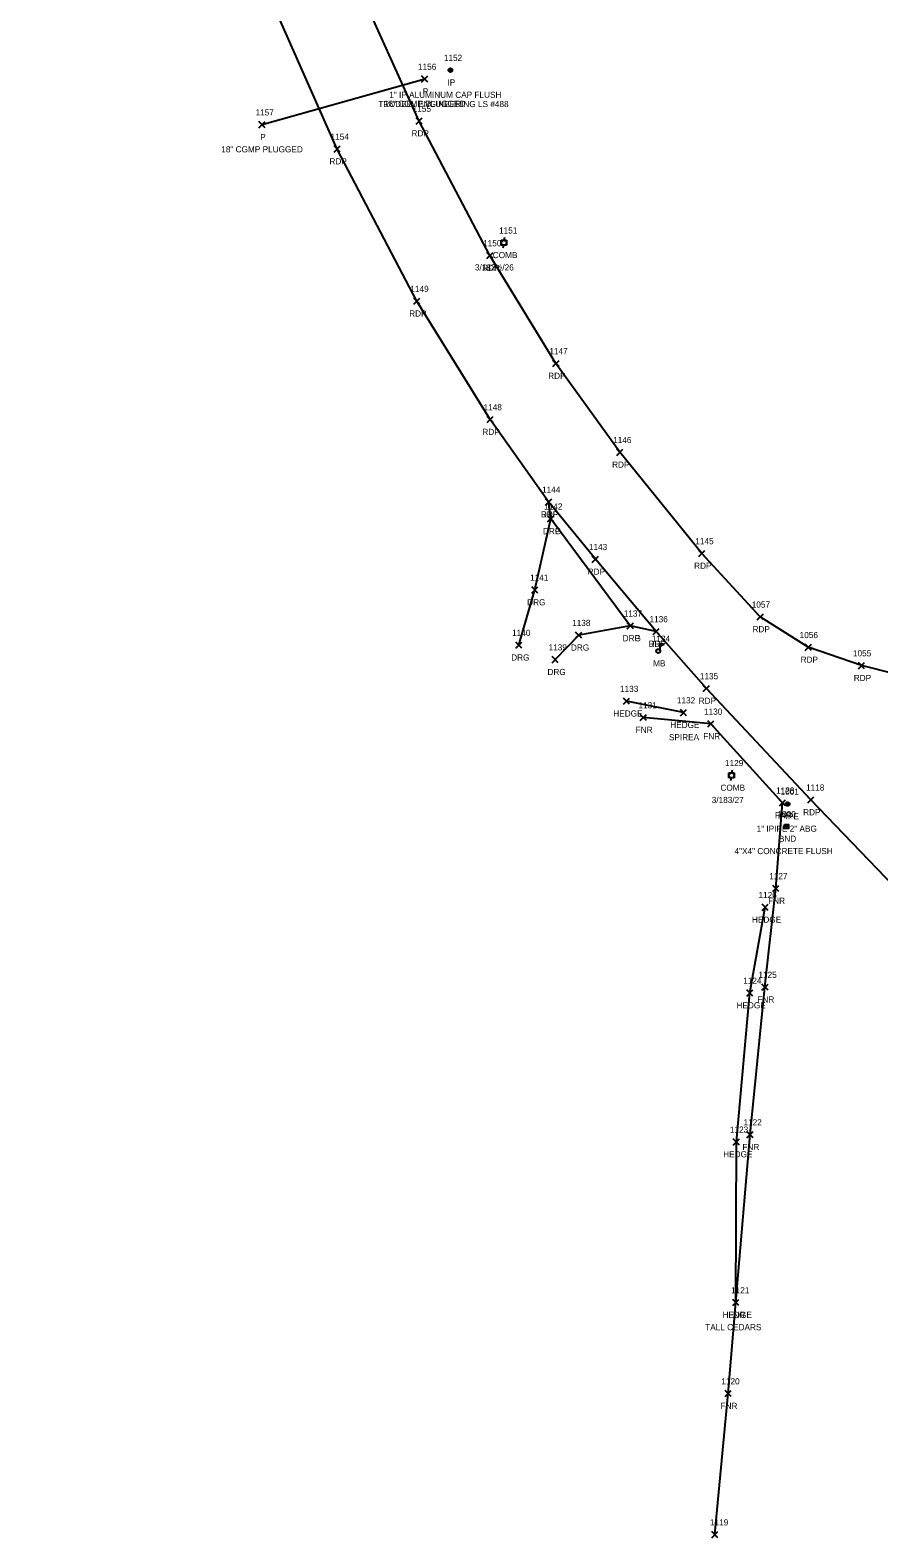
# Model space of a CAD drawing. Extents: x 1503463 to 1505240, y 712171 to 717196.
# Drawn here: x 1504621.3 to 1504897.3, y 713821.7 to 714311.7 of the extents above; entities that cross this region are included whole.
import ezdxf

# ---------------------------------------------------------------- set-up
doc = ezdxf.new("R2010")
doc.units = 0
for name, color, linetype in [('D_A', 7, 'Continuous'), ('D_C', 7, 'Continuous'), ('D_I', 7, 'Continuous'), ('D_TIC', 7, 'Continuous'), ('DCP', 7, 'Continuous'), ('L_A', 7, 'Continuous'), ('L_C', 7, 'Continuous'), ('L_I', 7, 'Continuous'), ('L_TIC', 7, 'Continuous'), ('LAHR', 7, 'Continuous'), ('LFNC', 7, 'Continuous'), ('LMB', 7, 'Continuous'), ('M_A', 7, 'Continuous'), ('M_C', 7, 'Continuous'), ('M_I', 7, 'Continuous'), ('MHBP', 7, 'Continuous'), ('MPIP', 7, 'Continuous'), ('MPIR', 7, 'Continuous'), ('P_A', 7, 'Continuous'), ('P_I', 7, 'Continuous'), ('P_TIC', 7, 'Continuous'), ('PET', 7, 'Continuous'), ('R_A', 7, 'Continuous'), ('R_I', 7, 'Continuous'), ('R_TIC', 7, 'Continuous'), ('RDG', 7, 'Continuous'), ('RDP', 7, 'Continuous'), ('U_A', 7, 'Continuous'), ('U_C', 7, 'Continuous'), ('U_I', 7, 'Continuous'), ('UP', 7, 'Continuous')]:
    doc.layers.add(name, color=color, linetype=linetype)

msp = doc.modelspace()

# ---------------------------------------------------------------- linework, layer by layer
at = {"layer": 'D_TIC'}
for points in [[(1504748.64, 714294.8), (1504750.64, 714296.8)], [(1504750.64, 714294.8), (1504748.64, 714296.8)], [(1504695.75, 714279.97), (1504697.75, 714281.97)], [(1504697.75, 714279.97), (1504695.75, 714281.97)]]:
    msp.add_lwpolyline(points, dxfattribs=at)
at = {"layer": 'DCP'}
msp.add_lwpolyline([(1504749.64, 714295.8), (1504696.75, 714280.97)], dxfattribs=at)
at = {"layer": 'L_TIC'}
for points in [[(1504814.26, 714092.64), (1504816.26, 714094.64)], [(1504816.26, 714092.64), (1504814.26, 714094.64)], [(1504819.72, 714087.31), (1504821.72, 714089.31)], [(1504821.72, 714087.31), (1504819.72, 714089.31)], [(1504832.78, 714088.92), (1504834.78, 714090.92)], [(1504834.78, 714088.92), (1504832.78, 714090.92)], [(1504841.67, 714085.25), (1504843.67, 714087.25)], [(1504843.67, 714085.25), (1504841.67, 714087.25)], [(1504865.01, 714059.61), (1504867.01, 714061.61)], [(1504867.01, 714059.61), (1504865.01, 714061.61)], [(1504862.79, 714031.77), (1504864.79, 714033.77)], [(1504864.79, 714031.77), (1504862.79, 714033.77)], [(1504859.36, 714025.65), (1504861.36, 714027.65)], [(1504861.36, 714025.65), (1504859.36, 714027.65)], [(1504859.27, 713999.7), (1504861.27, 714001.7)], [(1504861.27, 713999.7), (1504859.27, 714001.7)], [(1504854.33, 713997.81), (1504856.33, 713999.81)], [(1504856.33, 713997.81), (1504854.33, 713999.81)], [(1504854.42, 713951.78), (1504856.42, 713953.78)], [(1504856.42, 713951.78), (1504854.42, 713953.78)], [(1504849.99, 713949.4), (1504851.99, 713951.4)], [(1504851.99, 713949.4), (1504849.99, 713951.4)], [(1504849.82, 713897.2), (1504851.82, 713899.2)], [(1504851.82, 713897.2), (1504849.82, 713899.2)], [(1504849.82, 713897.2), (1504851.82, 713899.2)], [(1504851.82, 713897.2), (1504849.82, 713899.2)], [(1504847.3, 713867.63), (1504849.3, 713869.63)], [(1504849.3, 713867.63), (1504847.3, 713869.63)], [(1504842.97, 713821.78), (1504844.97, 713823.78)], [(1504844.97, 713821.78), (1504842.97, 713823.78)]]:
    msp.add_lwpolyline(points, dxfattribs=at)
at = {"layer": 'LAHR'}
for points in [[(1504833.78, 714089.92), (1504815.26, 714093.64)], [(1504850.82, 713898.2), (1504850.99, 713950.4), (1504855.33, 713998.81), (1504860.36, 714026.65)]]:
    msp.add_lwpolyline(points, dxfattribs=at)
at = {"layer": 'LFNC'}
msp.add_lwpolyline([(1504843.97, 713822.78), (1504848.3, 713868.63), (1504850.82, 713898.2), (1504855.42, 713952.78), (1504860.27, 714000.7), (1504863.79, 714032.77), (1504866.01, 714060.61), (1504842.67, 714086.25), (1504820.72, 714088.31)], dxfattribs=at)
at = {"layer": 'LMB'}
for p, q in [((1504825.59, 714109.93), (1504825.59, 714109.93)), ((1504826.24, 714112.53), (1504827.54, 714112.15)), ((1504826.25, 714109.94), (1504826.25, 714112.53)), ((1504826.25, 714111.63), (1504827.53, 714112.14))]:
    msp.add_line(p, q, dxfattribs=at)
msp.add_circle((1504825.59, 714109.93), 0.656, dxfattribs=at)
at = {"layer": 'MHBP'}
msp.add_lwpolyline([(1504866.68, 714053.56), (1504867.93, 714053.56), (1504867.93, 714052.31), (1504866.68, 714052.31)], close=True, dxfattribs=at)
msp.add_circle((1504867.31, 714052.93), 0.0833, dxfattribs=at)
at = {"layer": 'MPIP'}
for radius in [0.625, 0.0833]:
    msp.add_circle((1504867.63, 714060.21), radius, dxfattribs=at)
at = {"layer": 'MPIR'}
for radius in [0.625, 0.0833]:
    msp.add_circle((1504757.99, 714298.69), radius, dxfattribs=at)
at = {"layer": 'P_TIC'}
for points in [[(1504746.85, 714281.15), (1504748.85, 714283.15)], [(1504748.85, 714281.15), (1504746.85, 714283.15)], [(1504720.17, 714272.06), (1504722.17, 714274.06)], [(1504722.17, 714272.06), (1504720.17, 714274.06)], [(1504769.85, 714237.46), (1504771.85, 714239.46)], [(1504771.85, 714237.46), (1504769.85, 714239.46)], [(1504746.1, 714222.61), (1504748.1, 714224.61)], [(1504748.1, 714222.61), (1504746.1, 714224.61)], [(1504791.31, 714202.38), (1504793.31, 714204.38)], [(1504793.31, 714202.38), (1504791.31, 714204.38)], [(1504769.9, 714184.14), (1504771.9, 714186.14)], [(1504771.9, 714184.14), (1504769.9, 714186.14)], [(1504812.09, 714173.5), (1504814.09, 714175.5)], [(1504814.09, 714173.5), (1504812.09, 714175.5)], [(1504788.93, 714157.37), (1504790.93, 714159.37)], [(1504790.93, 714157.37), (1504788.93, 714159.37)], [(1504804.14, 714138.73), (1504806.14, 714140.73)], [(1504806.14, 714138.73), (1504804.14, 714140.73)], [(1504838.76, 714140.64), (1504840.76, 714142.64)], [(1504840.76, 714140.64), (1504838.76, 714142.64)], [(1504857.75, 714120.03), (1504859.75, 714122.03)], [(1504859.75, 714120.03), (1504857.75, 714122.03)], [(1504823.92, 714115.29), (1504825.92, 714117.29)], [(1504825.92, 714115.29), (1504823.92, 714117.29)], [(1504873.38, 714110.13), (1504875.38, 714112.13)], [(1504875.38, 714110.13), (1504873.38, 714112.13)], [(1504890.67, 714104.18), (1504892.67, 714106.18)], [(1504892.67, 714104.18), (1504890.67, 714106.18)], [(1504840.23, 714096.76), (1504842.23, 714098.76)], [(1504842.23, 714096.76), (1504840.23, 714098.76)], [(1504874.2, 714060.56), (1504876.2, 714062.56)], [(1504876.2, 714060.56), (1504874.2, 714062.56)]]:
    msp.add_lwpolyline(points, dxfattribs=at)
at = {"layer": 'PET'}
for points in [[(1505179.12, 714062.13), (1505162.73, 714064.23), (1505117.1, 714071.16), (1505063.73, 714078.62), (1505006.07, 714088.04), (1504974.7, 714091.87), (1504950.76, 714094.03), (1504913.58, 714099.65), (1504891.67, 714105.18), (1504874.38, 714111.13), (1504858.75, 714121.03), (1504839.76, 714141.64), (1504813.09, 714174.5), (1504792.31, 714203.38), (1504770.85, 714238.46), (1504747.85, 714282.15), (1504727.38, 714327.5), (1504712.05, 714367.82), (1504697.71, 714414.83), (1504685.11, 714458.97), (1504676.94, 714491.61), (1504665.42, 714541.32), (1504657.14, 714577.6), (1504649.31, 714613.48)], [(1505055.48, 713804.69), (1505035.67, 713846.75), (1505012.25, 713888.12), (1504984.81, 713930.29), (1504955.82, 713968.98), (1504925.45, 714007.09), (1504902.19, 714033.47), (1504875.2, 714061.56), (1504841.23, 714097.76), (1504824.92, 714116.29), (1504805.14, 714139.73), (1504789.93, 714158.37), (1504770.9, 714185.14), (1504747.1, 714223.61), (1504721.17, 714273.06), (1504701.58, 714317.3), (1504686.12, 714357.97), (1504670.15, 714407.6), (1504658, 714450.85), (1504649.24, 714485.62), (1504637.84, 714534.39), (1504628.86, 714571.69), (1504621.33, 714603.22)]]:
    msp.add_lwpolyline(points, dxfattribs=at)
at = {"layer": 'R_TIC'}
for points in [[(1504788.93, 714157.37), (1504790.93, 714159.37)], [(1504790.93, 714157.37), (1504788.93, 714159.37)], [(1504789.6, 714151.9), (1504791.6, 714153.9)], [(1504791.6, 714151.9), (1504789.6, 714153.9)], [(1504789.6, 714151.9), (1504791.6, 714153.9)], [(1504791.6, 714151.9), (1504789.6, 714153.9)], [(1504784.46, 714128.77), (1504786.46, 714130.77)], [(1504786.46, 714128.77), (1504784.46, 714130.77)], [(1504815.5, 714117.1), (1504817.5, 714119.1)], [(1504817.5, 714117.1), (1504815.5, 714119.1)], [(1504815.5, 714117.1), (1504817.5, 714119.1)], [(1504817.5, 714117.1), (1504815.5, 714119.1)], [(1504798.7, 714114.06), (1504800.7, 714116.06)], [(1504800.7, 714114.06), (1504798.7, 714116.06)], [(1504823.92, 714115.29), (1504825.92, 714117.29)], [(1504825.92, 714115.29), (1504823.92, 714117.29)], [(1504779.26, 714110.83), (1504781.26, 714112.83)], [(1504781.26, 714110.83), (1504779.26, 714112.83)], [(1504791.06, 714106.13), (1504793.06, 714108.13)], [(1504793.06, 714106.13), (1504791.06, 714108.13)]]:
    msp.add_lwpolyline(points, dxfattribs=at)
at = {"layer": 'RDG'}
for points in [[(1504780.26, 714111.83), (1504785.46, 714129.77), (1504790.6, 714152.9)], [(1504816.5, 714118.1), (1504799.7, 714115.06), (1504792.06, 714107.13)]]:
    msp.add_lwpolyline(points, dxfattribs=at)
at = {"layer": 'RDP'}
msp.add_lwpolyline([(1504824.92, 714116.29), (1504816.5, 714118.1), (1504790.6, 714152.9), (1504789.93, 714158.37)], dxfattribs=at)
at = {"layer": 'UP'}
for p, q in [((1504774.55, 714241.77), (1504774.55, 714243.44)), ((1504774.55, 714243.44), (1504776.22, 714243.44)), ((1504776.22, 714241.77), (1504774.55, 714241.77)), ((1504775.13, 714240.94), (1504775.38, 714241.77)), ((1504775.63, 714244.27), (1504775.38, 714243.44)), ((1504775.38, 714242.6), (1504775.38, 714242.6)), ((1504776.22, 714243.44), (1504776.22, 714241.77)), ((1504848.58, 714068.7), (1504848.58, 714070.37)), ((1504848.58, 714070.37), (1504850.25, 714070.37)), ((1504849.66, 714071.2), (1504849.41, 714070.37)), ((1504849.41, 714069.53), (1504849.41, 714069.53)), ((1504850.25, 714070.37), (1504850.25, 714068.7)), ((1504850.25, 714068.7), (1504848.58, 714068.7)), ((1504849.16, 714067.87), (1504849.41, 714068.7))]:
    msp.add_line(p, q, dxfattribs=at)
for centre in [(1504775.38, 714242.6), (1504849.41, 714069.53)]:
    msp.add_circle(centre, 0.833, dxfattribs=at)

# ---------------------------------------------------------------- texts
at = {"layer": 'D_A'}
for p in [(1504749.01, 714290.8), (1504696.13, 714275.97)]:
    msp.add_text('P', height=2, dxfattribs=at).set_placement(p)
at = {"layer": 'D_C'}
for p in [(1504736.37, 714286.8), (1504683.48, 714271.97)]:
    msp.add_text('18" CGMP PLUGGED', height=2, dxfattribs=at).set_placement(p)
at = {"layer": 'D_I'}
for s, p in [('1156', (1504747.46, 714298.8)), ('1157', (1504694.63, 714283.97))]:
    msp.add_text(s, height=2, dxfattribs=at).set_placement(p)
at = {"layer": 'L_A'}
for s, p in [('MB', (1504823.9, 714104.93)), ('HEDGE', (1504810.97, 714088.64)), ('FNR', (1504818.25, 714083.31)), ('HEDGE', (1504829.48, 714084.92)), ('FNR', (1504840.21, 714081.25)), ('FNR', (1504863.55, 714055.61)), ('FNR', (1504861.32, 714027.77)), ('HEDGE', (1504856.06, 714021.65)), ('FNR', (1504857.81, 713995.7)), ('HEDGE', (1504851.03, 713993.81)), ('HEDGE', (1504846.7, 713945.4)), ('FNR', (1504852.95, 713947.78)), ('HEDGE', (1504846.52, 713893.2)), ('FNR', (1504848.36, 713893.2)), ('FNR', (1504845.84, 713863.63))]:
    msp.add_text(s, height=2, dxfattribs=at).set_placement(p)
at = {"layer": 'L_C'}
for s, p in [('SPIREA', (1504829.06, 714080.92)), ('TALL CEDARS', (1504840.85, 713889.2))]:
    msp.add_text(s, height=2, dxfattribs=at).set_placement(p)
at = {"layer": 'L_I'}
for s, p in [('1134', (1504823.47, 714112.93)), ('1133', (1504813.14, 714096.64)), ('1132', (1504831.65, 714092.92)), ('1131', (1504819.16, 714091.31)), ('1130', (1504840.46, 714089.25)), ('1128', (1504863.89, 714063.61)), ('1127', (1504861.66, 714035.77)), ('1126', (1504858.18, 714029.65)), ('1125', (1504858.15, 714003.7)), ('1124', (1504853.21, 714001.81)), ('1122', (1504853.29, 713955.78)), ('1123', (1504848.87, 713953.4)), ('1121', (1504849.26, 713901.2)), ('1121', (1504849.26, 713901.2)), ('1120', (1504846.09, 713871.63)), ('1119', (1504842.4, 713825.78))]:
    msp.add_text(s, height=2, dxfattribs=at).set_placement(p)
at = {"layer": 'M_A'}
for s, p in [('IP', (1504757.04, 714293.69)), ('IPIPE', (1504864.47, 714055.21)), ('BND', (1504864.8, 714047.93))]:
    msp.add_text(s, height=2, dxfattribs=at).set_placement(p)
at = {"layer": 'M_C'}
for s, p in [('1" IP ALUMINUM CAP FLUSH', (1504738.11, 714289.69)), ('TRUDELL ENGINEERING LS #488', (1504734.56, 714286.69)), ('1" IPIPE 2" ABG', (1504857.56, 714051.21)), ('4"X4" CONCRETE FLUSH', (1504850.39, 714043.93))]:
    msp.add_text(s, height=2, dxfattribs=at).set_placement(p)
at = {"layer": 'M_I'}
for s, p in [('1152', (1504755.87, 714301.69)), ('1001', (1504865.35, 714063.21)), ('1000', (1504864.37, 714055.93))]:
    msp.add_text(s, height=2, dxfattribs=at).set_placement(p)
at = {"layer": 'P_A'}
for p in [(1504745.34, 714277.15), (1504718.66, 714268.06), (1504768.33, 714233.46), (1504744.59, 714218.61), (1504789.79, 714198.38), (1504768.39, 714180.14), (1504810.57, 714169.5), (1504787.41, 714153.37), (1504837.25, 714136.64), (1504802.63, 714134.73), (1504856.24, 714116.03), (1504822.41, 714111.29), (1504871.87, 714106.13), (1504889.16, 714100.18), (1504838.72, 714092.76), (1504872.69, 714056.56)]:
    msp.add_text('RDP', height=2, dxfattribs=at).set_placement(p)
at = {"layer": 'P_I'}
for s, p in [('1155', (1504745.73, 714285.15)), ('1154', (1504719.04, 714276.06)), ('1150', (1504768.63, 714241.46)), ('1149', (1504744.97, 714226.61)), ('1147', (1504790.18, 714206.38)), ('1148', (1504768.78, 714188.14)), ('1146', (1504810.91, 714177.5)), ('1144', (1504787.8, 714161.37)), ('1143', (1504803.02, 714142.73)), ('1145', (1504837.64, 714144.64)), ('1057', (1504855.98, 714124.03)), ('1136', (1504822.74, 714119.29)), ('1056', (1504871.56, 714114.13)), ('1055', (1504888.9, 714108.18)), ('1135', (1504839.11, 714100.76)), ('1118', (1504873.64, 714064.56))]:
    msp.add_text(s, height=2, dxfattribs=at).set_placement(p)
at = {"layer": 'R_A'}
for s, p in [('DRP', (1504787.41, 714153.37)), ('DRG', (1504788.09, 714147.9)), ('DRP', (1504788.09, 714147.9)), ('DRG', (1504782.95, 714124.77)), ('DRG', (1504813.99, 714113.1)), ('DRP', (1504813.99, 714113.1)), ('DRG', (1504777.75, 714106.83)), ('DRG', (1504797.19, 714110.06)), ('DRP', (1504822.41, 714111.29)), ('DRG', (1504789.55, 714102.13))]:
    msp.add_text(s, height=2, dxfattribs=at).set_placement(p)
at = {"layer": 'R_I'}
for s, p in [('1144', (1504787.8, 714161.37)), ('1142', (1504788.47, 714155.9)), ('1142', (1504788.47, 714155.9)), ('1141', (1504783.9, 714132.77)), ('1138', (1504797.58, 714118.06)), ('1137', (1504814.37, 714121.1)), ('1137', (1504814.37, 714121.1)), ('1136', (1504822.74, 714119.29)), ('1140', (1504778.05, 714114.83)), ('1139', (1504789.92, 714110.13))]:
    msp.add_text(s, height=2, dxfattribs=at).set_placement(p)
at = {"layer": 'U_A'}
for p in [(1504771.77, 714237.6), (1504845.8, 714064.53)]:
    msp.add_text('COMB', height=2, dxfattribs=at).set_placement(p)
at = {"layer": 'U_C'}
for s, p in [('3/182½/26', (1504765.96, 714233.6)), ('3/183/27', (1504842.97, 714060.53))]:
    msp.add_text(s, height=2, dxfattribs=at).set_placement(p)
at = {"layer": 'U_I'}
for s, p in [('1151', (1504773.82, 714245.6)), ('1129', (1504847.28, 714072.53))]:
    msp.add_text(s, height=2, dxfattribs=at).set_placement(p)

doc.saveas('drawing.dxf')
